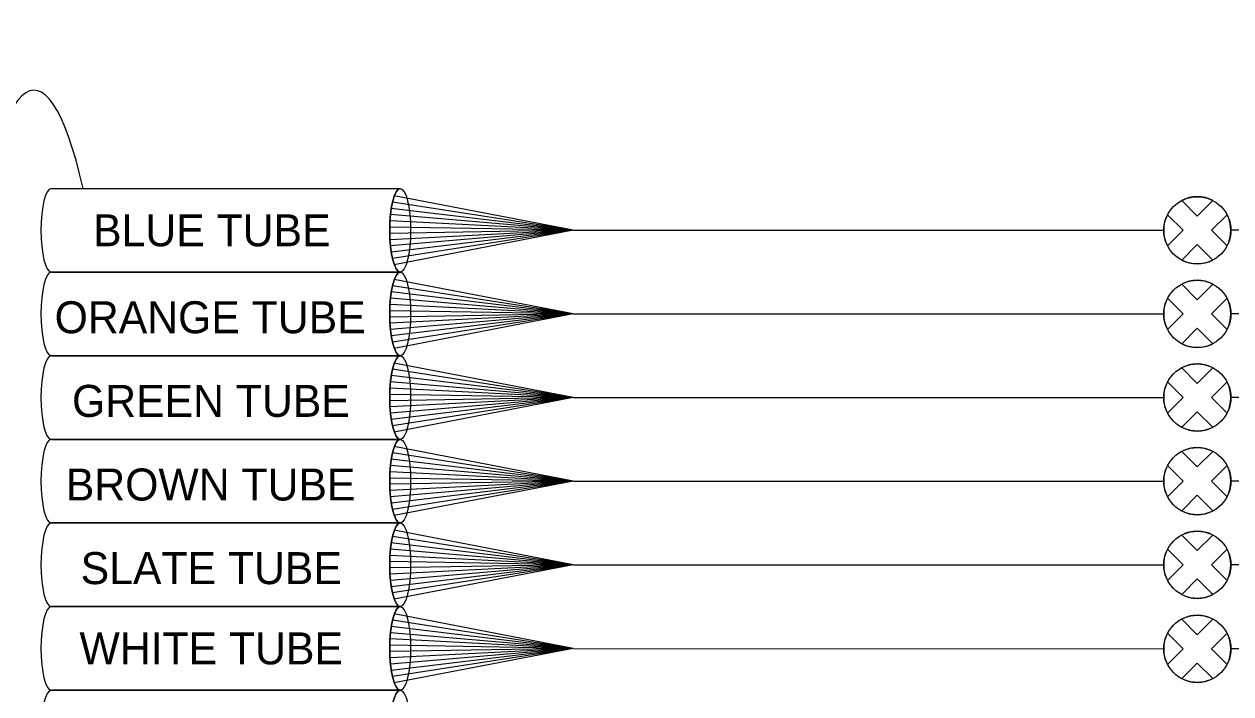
# Model space of a CAD drawing. Extents: x 1805893 to 1833564, y 708898 to 716199.
# Drawn here: x 1831652.5 to 1831739.1, y 716072.6 to 716120.6 of the extents above; entities that cross this region are included whole.
import ezdxf

# ---------------------------------------------------------------- set-up
doc = ezdxf.new("R2010")
doc.units = 0
doc.layers.add('SH_Data', color=7, linetype='Continuous')

msp = doc.modelspace()

# ---------------------------------------------------------------- linework, layer by layer
at = {"layer": 'SH_Data'}
for p, q in [((1831654.439, 716108.828), (1831679.489, 716108.828)), ((1831654.439, 716108.828), (1831679.489, 716108.828)), ((1831691.91, 716105.828), (1831678.936, 716107.853)), ((1831691.91, 716105.828), (1831679.066, 716108.303)), ((1831735.608, 716107.964), (1831736.727, 716106.846)), ((1831736.727, 716106.846), (1831735.608, 716107.964)), ((1831736.727, 716106.846), (1831737.846, 716107.964)), ((1831737.846, 716107.964), (1831736.727, 716106.846)), ((1831691.91, 716105.828), (1831678.794, 716106.953)), ((1831691.91, 716105.828), (1831678.851, 716107.403)), ((1831734.591, 716106.947), (1831735.71, 716105.828)), ((1831734.591, 716106.947), (1831735.71, 716105.828)), ((1831737.744, 716105.828), (1831738.863, 716106.947)), ((1831737.744, 716105.828), (1831738.863, 716106.947)), ((1831691.91, 716105.828), (1831678.741, 716106.053)), ((1831691.91, 716105.828), (1831678.759, 716106.503)), ((1831691.91, 716105.828), (1831678.741, 716105.603)), ((1831691.91, 716105.828), (1831678.759, 716105.153)), ((1831691.91, 716105.828), (1831678.794, 716104.703)), ((1831691.91, 716105.828), (1831678.851, 716104.253)), ((1831691.91, 716105.828), (1831678.936, 716103.803)), ((1831691.91, 716105.828), (1831679.066, 716103.353)), ((1831691.91, 716105.828), (1831734.316, 716105.828)), ((1831734.591, 716104.71), (1831735.71, 716105.828)), ((1831735.71, 716105.828), (1831734.591, 716104.71)), ((1831737.744, 716105.828), (1831738.863, 716104.71)), ((1831738.863, 716104.71), (1831737.744, 716105.828)), ((1831781.545, 716105.828), (1831739.139, 716105.828)), ((1831735.608, 716103.692), (1831736.727, 716104.811)), ((1831735.608, 716103.692), (1831736.727, 716104.811)), ((1831736.727, 716104.811), (1831737.846, 716103.692)), ((1831736.727, 716104.811), (1831737.846, 716103.692)), ((1831679.489, 716102.828), (1831654.439, 716102.828)), ((1831654.439, 716102.828), (1831679.489, 716102.828)), ((1831691.91, 716099.828), (1831678.936, 716101.853)), ((1831691.91, 716099.828), (1831679.066, 716102.303)), ((1831735.608, 716101.964), (1831736.727, 716100.846)), ((1831736.727, 716100.846), (1831735.608, 716101.964)), ((1831736.727, 716100.846), (1831737.846, 716101.964)), ((1831737.846, 716101.964), (1831736.727, 716100.846)), ((1831691.91, 716099.828), (1831678.794, 716100.953)), ((1831691.91, 716099.828), (1831678.851, 716101.403)), ((1831734.591, 716100.947), (1831735.71, 716099.828)), ((1831734.591, 716100.947), (1831735.71, 716099.828)), ((1831737.744, 716099.828), (1831738.863, 716100.947)), ((1831737.744, 716099.828), (1831738.863, 716100.947)), ((1831691.91, 716099.828), (1831678.741, 716100.053)), ((1831691.91, 716099.828), (1831678.741, 716099.603)), ((1831691.91, 716099.828), (1831678.759, 716100.503)), ((1831691.91, 716099.828), (1831678.759, 716099.153)), ((1831691.91, 716099.828), (1831678.794, 716098.703)), ((1831691.91, 716099.828), (1831678.851, 716098.253)), ((1831691.91, 716099.828), (1831678.936, 716097.803)), ((1831691.91, 716099.828), (1831679.066, 716097.353)), ((1831691.91, 716099.828), (1831734.316, 716099.828)), ((1831734.591, 716098.71), (1831735.71, 716099.828)), ((1831735.71, 716099.828), (1831734.591, 716098.71)), ((1831737.744, 716099.828), (1831738.863, 716098.71)), ((1831738.863, 716098.71), (1831737.744, 716099.828)), ((1831781.545, 716099.828), (1831739.139, 716099.828)), ((1831735.608, 716097.692), (1831736.727, 716098.811)), ((1831735.608, 716097.692), (1831736.727, 716098.811)), ((1831736.727, 716098.811), (1831737.846, 716097.692)), ((1831736.727, 716098.811), (1831737.846, 716097.692)), ((1831654.439, 716096.828), (1831679.489, 716096.828)), ((1831679.489, 716096.828), (1831654.439, 716096.828)), ((1831691.91, 716093.828), (1831678.936, 716095.853)), ((1831691.91, 716093.828), (1831679.066, 716096.303)), ((1831735.608, 716095.964), (1831736.727, 716094.846)), ((1831736.727, 716094.846), (1831735.608, 716095.964)), ((1831736.727, 716094.846), (1831737.846, 716095.964)), ((1831737.846, 716095.964), (1831736.727, 716094.846)), ((1831691.91, 716093.828), (1831678.794, 716094.953)), ((1831691.91, 716093.828), (1831678.851, 716095.403)), ((1831734.591, 716094.947), (1831735.71, 716093.828)), ((1831734.591, 716094.947), (1831735.71, 716093.828)), ((1831737.744, 716093.828), (1831738.863, 716094.947)), ((1831737.744, 716093.828), (1831738.863, 716094.947)), ((1831691.91, 716093.828), (1831678.741, 716094.053)), ((1831691.91, 716093.828), (1831678.741, 716093.603)), ((1831691.91, 716093.828), (1831678.759, 716094.503)), ((1831691.91, 716093.828), (1831678.759, 716093.153)), ((1831691.91, 716093.828), (1831678.794, 716092.703)), ((1831691.91, 716093.828), (1831678.851, 716092.253)), ((1831691.91, 716093.828), (1831678.936, 716091.803)), ((1831691.91, 716093.828), (1831679.066, 716091.353)), ((1831691.91, 716093.828), (1831734.316, 716093.828)), ((1831734.591, 716092.71), (1831735.71, 716093.828)), ((1831735.71, 716093.828), (1831734.591, 716092.71)), ((1831737.744, 716093.828), (1831738.863, 716092.71)), ((1831738.863, 716092.71), (1831737.744, 716093.828)), ((1831781.545, 716093.828), (1831739.139, 716093.828)), ((1831735.608, 716091.692), (1831736.727, 716092.811)), ((1831735.608, 716091.692), (1831736.727, 716092.811)), ((1831736.727, 716092.811), (1831737.846, 716091.692)), ((1831736.727, 716092.811), (1831737.846, 716091.692)), ((1831679.489, 716090.828), (1831654.439, 716090.828)), ((1831654.439, 716090.828), (1831679.489, 716090.828)), ((1831691.91, 716087.828), (1831679.066, 716090.303)), ((1831691.91, 716087.828), (1831678.936, 716089.853)), ((1831735.608, 716089.964), (1831736.727, 716088.846)), ((1831736.727, 716088.846), (1831735.608, 716089.964)), ((1831736.727, 716088.846), (1831737.846, 716089.964)), ((1831737.846, 716089.964), (1831736.727, 716088.846)), ((1831691.91, 716087.828), (1831678.794, 716088.953)), ((1831691.91, 716087.828), (1831678.851, 716089.403)), ((1831734.591, 716088.947), (1831735.71, 716087.828)), ((1831734.591, 716088.947), (1831735.71, 716087.828)), ((1831737.744, 716087.828), (1831738.863, 716088.947)), ((1831737.744, 716087.828), (1831738.863, 716088.947)), ((1831691.91, 716087.828), (1831678.741, 716088.053)), ((1831691.91, 716087.828), (1831678.741, 716087.603)), ((1831691.91, 716087.828), (1831678.759, 716088.503)), ((1831691.91, 716087.828), (1831678.759, 716087.153)), ((1831691.91, 716087.828), (1831678.794, 716086.703)), ((1831691.91, 716087.828), (1831678.851, 716086.253)), ((1831691.91, 716087.828), (1831678.936, 716085.803)), ((1831691.91, 716087.828), (1831679.066, 716085.353)), ((1831691.91, 716087.828), (1831734.316, 716087.828)), ((1831734.591, 716086.71), (1831735.71, 716087.828)), ((1831735.71, 716087.828), (1831734.591, 716086.71)), ((1831737.744, 716087.828), (1831738.863, 716086.71)), ((1831738.863, 716086.71), (1831737.744, 716087.828)), ((1831781.545, 716087.828), (1831739.139, 716087.828)), ((1831735.608, 716085.692), (1831736.727, 716086.811)), ((1831735.608, 716085.692), (1831736.727, 716086.811)), ((1831736.727, 716086.811), (1831737.846, 716085.692)), ((1831736.727, 716086.811), (1831737.846, 716085.692)), ((1831679.489, 716084.828), (1831654.439, 716084.828)), ((1831654.439, 716084.828), (1831679.489, 716084.828)), ((1831691.91, 716081.828), (1831679.066, 716084.303)), ((1831691.91, 716081.828), (1831678.851, 716083.403)), ((1831691.91, 716081.828), (1831678.936, 716083.853)), ((1831735.608, 716083.964), (1831736.727, 716082.846)), ((1831736.727, 716082.846), (1831735.608, 716083.964)), ((1831736.727, 716082.846), (1831737.846, 716083.964)), ((1831737.846, 716083.964), (1831736.727, 716082.846)), ((1831691.91, 716081.828), (1831678.759, 716082.503)), ((1831691.91, 716081.828), (1831678.794, 716082.953)), ((1831734.591, 716082.947), (1831735.71, 716081.828)), ((1831734.591, 716082.947), (1831735.71, 716081.828)), ((1831737.744, 716081.828), (1831738.863, 716082.947)), ((1831737.744, 716081.828), (1831738.863, 716082.947)), ((1831691.91, 716081.828), (1831678.741, 716082.053)), ((1831691.91, 716081.828), (1831678.741, 716081.603)), ((1831691.91, 716081.828), (1831678.759, 716081.153)), ((1831691.91, 716081.828), (1831678.794, 716080.703)), ((1831691.91, 716081.828), (1831678.851, 716080.253)), ((1831691.91, 716081.828), (1831678.936, 716079.803)), ((1831691.91, 716081.828), (1831679.066, 716079.353)), ((1831691.91, 716081.828), (1831734.316, 716081.828)), ((1831734.591, 716080.71), (1831735.71, 716081.828)), ((1831735.71, 716081.828), (1831734.591, 716080.71)), ((1831737.744, 716081.828), (1831738.863, 716080.71)), ((1831738.863, 716080.71), (1831737.744, 716081.828)), ((1831781.545, 716081.828), (1831739.139, 716081.828)), ((1831735.608, 716079.692), (1831736.727, 716080.811)), ((1831735.608, 716079.692), (1831736.727, 716080.811)), ((1831736.727, 716080.811), (1831737.846, 716079.692)), ((1831736.727, 716080.811), (1831737.846, 716079.692)), ((1831679.489, 716078.828), (1831654.439, 716078.828)), ((1831654.439, 716078.828), (1831679.489, 716078.828)), ((1831691.91, 716075.828), (1831679.066, 716078.303)), ((1831691.91, 716075.828), (1831678.851, 716077.403)), ((1831691.91, 716075.828), (1831678.936, 716077.853)), ((1831735.608, 716077.93), (1831736.727, 716076.811)), ((1831736.727, 716076.811), (1831735.608, 716077.93)), ((1831736.727, 716076.811), (1831737.846, 716077.93)), ((1831737.846, 716077.93), (1831736.727, 716076.811)), ((1831691.91, 716075.828), (1831678.759, 716076.503)), ((1831691.91, 716075.828), (1831678.794, 716076.953)), ((1831734.591, 716076.913), (1831735.71, 716075.794)), ((1831734.591, 716076.913), (1831735.71, 716075.794)), ((1831737.744, 716075.794), (1831738.863, 716076.913)), ((1831737.744, 716075.794), (1831738.863, 716076.913)), ((1831691.91, 716075.828), (1831678.741, 716076.053)), ((1831691.91, 716075.828), (1831678.741, 716075.603)), ((1831691.91, 716075.828), (1831678.759, 716075.153)), ((1831691.91, 716075.828), (1831678.794, 716074.703)), ((1831691.91, 716075.828), (1831678.851, 716074.253)), ((1831691.91, 716075.828), (1831678.936, 716073.803)), ((1831691.91, 716075.828), (1831679.066, 716073.353)), ((1831691.91, 716075.812), (1831734.316, 716075.795)), ((1831734.591, 716074.675), (1831735.71, 716075.794)), ((1831735.71, 716075.794), (1831734.591, 716074.675)), ((1831737.744, 716075.794), (1831738.863, 716074.675)), ((1831738.863, 716074.675), (1831737.744, 716075.794)), ((1831781.545, 716075.801), (1831739.139, 716075.784)), ((1831735.608, 716073.658), (1831736.727, 716074.777)), ((1831735.608, 716073.658), (1831736.727, 716074.777)), ((1831736.727, 716074.777), (1831737.846, 716073.658)), ((1831736.727, 716074.777), (1831737.846, 716073.658)), ((1831679.489, 716072.828), (1831654.439, 716072.828)), ((1831654.439, 716072.828), (1831679.489, 716072.828))]:
    msp.add_line(p, q, dxfattribs=at)
for centre in [(1831736.727, 716105.828), (1831736.727, 716099.828), (1831736.727, 716093.828), (1831736.727, 716087.828), (1831736.727, 716081.828), (1831736.727, 716075.794)]:
    msp.add_circle(centre, 2.411, dxfattribs=at)
for centre, start, end in [((1831736.727, 716105.828), 62.353, 117.647), ((1831736.727, 716105.828), 152.353, 207.647), ((1831736.727, 716105.828), 332.353, 27.647), ((1831736.727, 716105.828), 242.353, 297.647), ((1831736.727, 716099.828), 62.353, 117.647), ((1831736.727, 716099.828), 152.353, 207.647), ((1831736.727, 716099.828), 332.353, 27.647), ((1831736.727, 716099.828), 242.353, 297.647), ((1831736.727, 716093.828), 62.353, 117.647), ((1831736.727, 716093.828), 152.353, 207.647), ((1831736.727, 716093.828), 332.353, 27.647), ((1831736.727, 716093.828), 242.353, 297.647), ((1831736.727, 716087.828), 62.353, 117.647), ((1831736.727, 716087.828), 152.353, 207.647), ((1831736.727, 716087.828), 332.353, 27.647), ((1831736.727, 716087.828), 242.353, 297.647), ((1831736.727, 716081.828), 62.353, 117.647), ((1831736.727, 716081.828), 152.353, 207.647), ((1831736.727, 716081.828), 332.353, 27.647), ((1831736.727, 716081.828), 242.353, 297.647), ((1831736.727, 716075.794), 62.353, 117.647), ((1831736.727, 716075.794), 152.353, 207.647), ((1831736.727, 716075.794), 332.353, 27.647), ((1831736.727, 716075.794), 242.353, 297.647)]:
    msp.add_arc(centre, 2.411, start, end, dxfattribs=at)
for centre, major_axis, ratio, start_param, end_param in [((1831653.192, 716072.828), (0, -43.047), 0.149566, 2.561295, 6.863483), ((1831654.439, 716105.828), (0, -3), 0.25, 3.141593, 6.283185), ((1831654.439, 716105.828), (0, -3), 0.25, 3.141593, 6.283185), ((1831679.489, 716105.828), (0, -3), 0.25, 3.141593, 6.283185), ((1831654.439, 716099.828), (0, -3), 0.25, 3.141593, 6.283185), ((1831654.439, 716099.828), (0, -3), 0.25, 3.141593, 6.283185), ((1831679.489, 716099.828), (0, -3), 0.25, 3.141593, 6.283185), ((1831654.439, 716093.828), (0, -3), 0.25, 3.141593, 6.283185), ((1831654.439, 716093.828), (0, -3), 0.25, 3.141593, 6.283185), ((1831679.489, 716093.828), (0, -3), 0.25, 3.141593, 6.283185), ((1831654.439, 716087.828), (0, -3), 0.25, 3.141593, 6.283185), ((1831654.439, 716087.828), (0, -3), 0.25, 3.141593, 6.283185), ((1831679.489, 716087.828), (0, -3), 0.25, 3.141593, 6.283185), ((1831654.439, 716081.828), (0, -3), 0.25, 3.141593, 6.283185), ((1831654.439, 716081.828), (0, -3), 0.25, 3.141593, 6.283185), ((1831679.489, 716081.828), (0, -3), 0.25, 3.141593, 6.283185), ((1831654.439, 716075.828), (0, -3), 0.25, 3.141593, 6.283185), ((1831654.439, 716075.828), (0, -3), 0.25, 3.141593, 6.283185), ((1831679.489, 716075.828), (0, -3), 0.25, 3.141593, 6.283185), ((1831654.439, 716069.828), (0, -3), 0.25, 3.141593, 6.283185), ((1831654.439, 716069.828), (0, -3), 0.25, 3.141593, 6.283185), ((1831679.489, 716069.828), (0, -3), 0.25, 3.141593, 6.283185)]:
    msp.add_ellipse(centre, major_axis=major_axis, ratio=ratio, start_param=start_param, end_param=end_param, dxfattribs=at)
for centre in [(1831679.489, 716105.828), (1831679.489, 716099.828), (1831679.489, 716093.828), (1831679.489, 716087.828), (1831679.489, 716081.828), (1831679.489, 716075.828), (1831679.489, 716069.828)]:
    msp.add_ellipse(centre, major_axis=(0, -3), ratio=0.25, dxfattribs=at)

# ---------------------------------------------------------------- texts
for s, height, p in [('BLUE TUBE', 2.2947, (1831657.434, 716104.681)), ('ORANGE TUBE', 2.29468, (1831654.674, 716098.44)), ('GREEN TUBE', 2.2947, (1831655.921, 716092.44)), ('BROWN TUBE', 2.2947, (1831655.477, 716086.44)), ('SLATE TUBE', 2.2947, (1831656.543, 716080.44)), ('WHITE TUBE', 2.2947, (1831656.457, 716074.681))]:
    msp.add_text(s, height=height, dxfattribs=at).set_placement(p)

doc.saveas('drawing.dxf')
